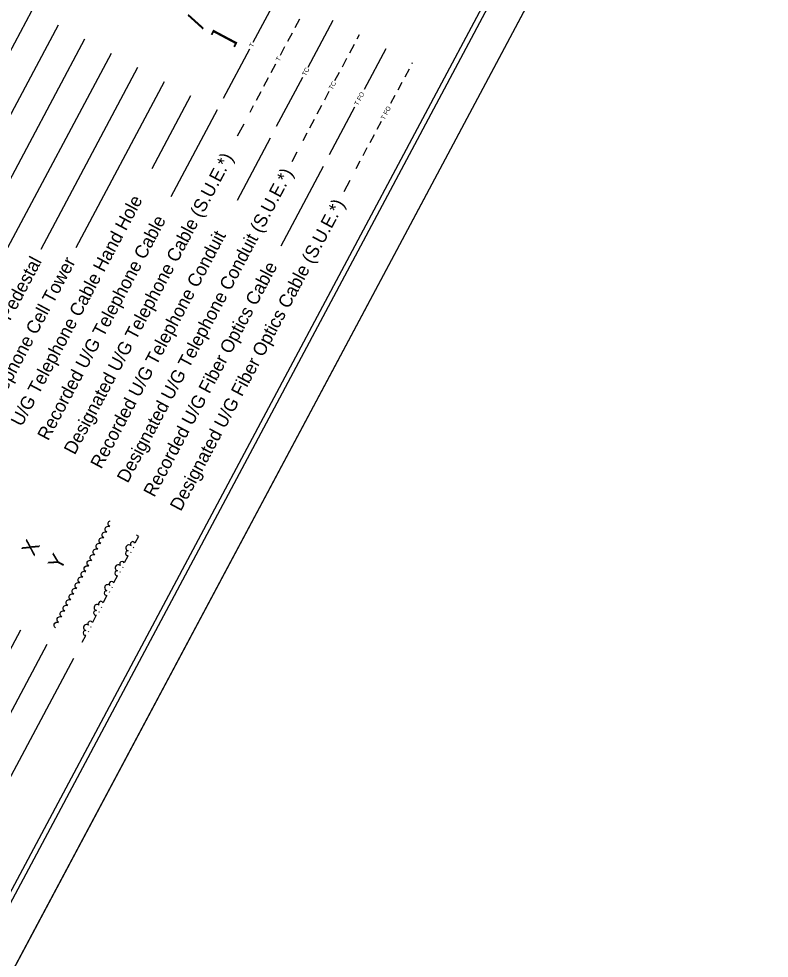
# Model space of a CAD drawing. Extents: x 1970823 to 1988115, y 770601 to 786368.
# Drawn here: x 1980773 to 1981272, y 778443 to 779069 of the extents above; entities that cross this region are included whole.
import ezdxf

# ---------------------------------------------------------------- set-up
doc = ezdxf.new("R2010")
doc.units = 0
for name, color, linetype in [('Sheet Cutting Line CELL', 7, 'Continuous'), ('Sheet Plot Border Inside CELL', 7, 'Continuous'), ('Sheet Plot Border Outside CELL', 7, 'Continuous'), ('Sheet Symbology CELL', 7, 'Continuous')]:
    doc.layers.add(name, color=color, linetype=linetype)

msp = doc.modelspace()

# ---------------------------------------------------------------- linework, layer by layer
at = {"layer": 'Sheet Cutting Line CELL'}
msp.add_line((1980480.43, 777893.78), (1981272.39, 779379.94), dxfattribs=at)
at = {"layer": 'Sheet Plot Border Inside CELL'}
msp.add_lwpolyline([(1980466.73, 777915.81), (1981250.46, 779386.52), (1980319.32, 779882.72), (1979535.59, 778412.01)], close=True, dxfattribs=at)
at = {"layer": 'Sheet Plot Border Outside CELL'}
msp.add_lwpolyline([(1980480.43, 777893.78), (1981272.39, 779379.94), (1980301.63, 779897.25), (1979509.67, 778411.1)], close=True, dxfattribs=at)
at = {"layer": 'Sheet Symbology CELL'}
for p, q in [((1980928.96, 779052.97), (1980946.77, 779086.4)), ((1980781.36, 779073.68), (1980728.74, 778974.94)), ((1980799.01, 779064.28), (1980751.01, 778974.21)), ((1980956.86, 779062.81), (1980959.92, 779068.54)), ((1980965.42, 779036.33), (1980982.07, 779067.59)), ((1980951.92, 779053.54), (1980954.98, 779059.28)), ((1980998.12, 779055.17), (1980999.72, 779058.18)), ((1980816.66, 779054.87), (1980751.82, 778933.21)), ((1980993.18, 779045.9), (1980996.24, 779051.64)), ((1980834.31, 779045.47), (1980763.53, 778912.65)), ((1980909.15, 779015.8), (1980926.61, 779048.56)), ((1980946.99, 779044.27), (1980950.04, 779050.01)), ((1981002.97, 779021.75), (1981017.37, 779048.78)), ((1980940.92, 779032.89), (1980943.98, 779038.63)), ((1980988.24, 779036.64), (1980991.3, 779042.37)), ((1981034.71, 779038.78), (1981035.02, 779039.37)), ((1980851.96, 779036.06), (1980787.45, 778915.01)), ((1980983.3, 779027.37), (1980986.36, 779033.11)), ((1981030.01, 779029.96), (1981032.83, 779035.25)), ((1980869.61, 779026.65), (1980810.72, 778916.14)), ((1980935.98, 779023.62), (1980939.04, 779029.36)), ((1980944.45, 778996.99), (1980961.89, 779029.72)), ((1981025.31, 779021.13), (1981028.13, 779026.43)), ((1980931.04, 779014.36), (1980934.1, 779020.09)), ((1980976.48, 779014.57), (1980979.54, 779020.31)), ((1980887.26, 779017.25), (1980861.38, 778968.68)), ((1981020.6, 779012.31), (1981023.43, 779017.6)), ((1980904.91, 779007.84), (1980874.08, 778949.98)), ((1980926.8, 779006.39), (1980929.16, 779010.83)), ((1980971.55, 779005.31), (1980974.6, 779011.04)), ((1980979.75, 778978.17), (1980996.62, 779009.83)), ((1980966.61, 778996.04), (1980969.67, 779001.78)), ((1980922.56, 778998.44), (1980918.26, 778990.37)), ((1981011.43, 778995.1), (1981014.25, 779000.4)), ((1980940.21, 778989.03), (1980918.14, 778947.62)), ((1980962.1, 778987.58), (1980964.73, 778992.51)), ((1981006.73, 778986.28), (1981009.55, 778991.57)), ((1981002.03, 778977.45), (1981004.85, 778982.75)), ((1980957.86, 778979.63), (1980954.54, 778973.39)), ((1980975.51, 778970.22), (1980947.28, 778917.25)), ((1980997.4, 778968.77), (1981000.15, 778973.92)), ((1980993.16, 778960.81), (1980989.14, 778953.26)), ((1980832.36, 778732.9), (1980832.8, 778733.74)), ((1980832.38, 778731.99), (1980832.36, 778732.9)), ((1980832.67, 778731.15), (1980832.38, 778731.99)), ((1980832.8, 778733.74), (1980833.62, 778734.21)), ((1980833.62, 778734.21), (1980833.69, 778734.23)), ((1980828.36, 778725.4), (1980828.81, 778726.24)), ((1980828.81, 778726.24), (1980829.62, 778726.71)), ((1980829.62, 778726.71), (1980830.46, 778726.89)), ((1980830.36, 778729.15), (1980830.81, 778729.99)), ((1980830.38, 778728.24), (1980830.36, 778729.15)), ((1980830.67, 778727.4), (1980830.38, 778728.24)), ((1980830.46, 778726.89), (1980831.3, 778726.67)), ((1980831.37, 778726.69), (1980830.67, 778727.4)), ((1980830.81, 778729.99), (1980831.62, 778730.46)), ((1980831.62, 778730.46), (1980832.46, 778730.64)), ((1980832.46, 778730.64), (1980833.3, 778730.42)), ((1980833.37, 778730.44), (1980832.67, 778731.15)), ((1980826.36, 778721.65), (1980826.81, 778722.49)), ((1980826.38, 778720.73), (1980826.36, 778721.65)), ((1980826.67, 778719.9), (1980826.38, 778720.73)), ((1980827.37, 778719.19), (1980826.67, 778719.9)), ((1980826.81, 778722.49), (1980827.63, 778722.96)), ((1980827.63, 778722.96), (1980828.46, 778723.14)), ((1980828.38, 778724.49), (1980828.36, 778725.4)), ((1980828.67, 778723.65), (1980828.38, 778724.49)), ((1980828.46, 778723.14), (1980829.3, 778722.92)), ((1980829.37, 778722.94), (1980828.67, 778723.65)), ((1980850.31, 778719.71), (1980852.66, 778724.12)), ((1980822.36, 778714.15), (1980822.81, 778714.99)), ((1980822.38, 778713.23), (1980822.36, 778714.15)), ((1980822.68, 778712.4), (1980822.38, 778713.23)), ((1980822.81, 778714.99), (1980823.63, 778715.46)), ((1980823.63, 778715.46), (1980824.46, 778715.64)), ((1980824.36, 778717.9), (1980824.81, 778718.74)), ((1980824.38, 778716.98), (1980824.36, 778717.9)), ((1980824.67, 778716.15), (1980824.38, 778716.98)), ((1980824.46, 778715.64), (1980825.3, 778715.42)), ((1980825.37, 778715.44), (1980824.67, 778716.15)), ((1980824.81, 778718.74), (1980825.63, 778719.21)), ((1980825.63, 778719.21), (1980826.46, 778719.39)), ((1980826.46, 778719.39), (1980827.3, 778719.17)), ((1980847.44, 778713.25), (1980847.67, 778713.7)), ((1980849.08, 778716.34), (1980849.32, 778716.78)), ((1980818.37, 778706.65), (1980818.81, 778707.49)), ((1980818.81, 778707.49), (1980819.63, 778707.96)), ((1980819.63, 778707.96), (1980820.46, 778708.14)), ((1980820.37, 778710.4), (1980820.81, 778711.24)), ((1980820.39, 778709.48), (1980820.37, 778710.4)), ((1980820.68, 778708.65), (1980820.39, 778709.48)), ((1980820.46, 778708.14), (1980821.31, 778707.92)), ((1980821.37, 778707.94), (1980820.68, 778708.65)), ((1980820.81, 778711.24), (1980821.63, 778711.71)), ((1980821.63, 778711.71), (1980822.46, 778711.89)), ((1980822.46, 778711.89), (1980823.31, 778711.67)), ((1980823.37, 778711.69), (1980822.68, 778712.4)), ((1980843.26, 778706.47), (1980845.61, 778710.89)), ((1980816.37, 778702.9), (1980816.81, 778703.74)), ((1980816.39, 778701.98), (1980816.37, 778702.9)), ((1980816.68, 778701.15), (1980816.39, 778701.98)), ((1980817.38, 778700.43), (1980816.68, 778701.15)), ((1980816.81, 778703.74), (1980817.63, 778704.21)), ((1980817.63, 778704.21), (1980818.46, 778704.39)), ((1980818.39, 778705.73), (1980818.37, 778706.65)), ((1980818.68, 778704.9), (1980818.39, 778705.73)), ((1980818.46, 778704.39), (1980819.31, 778704.16)), ((1980819.38, 778704.19), (1980818.68, 778704.9)), ((1980842.03, 778703.1), (1980842.26, 778703.55)), ((1980812.37, 778695.4), (1980812.82, 778696.24)), ((1980812.39, 778694.48), (1980812.37, 778695.4)), ((1980812.68, 778693.64), (1980812.39, 778694.48)), ((1980812.82, 778696.24), (1980813.63, 778696.71)), ((1980813.63, 778696.71), (1980814.47, 778696.89)), ((1980814.37, 778699.15), (1980814.82, 778699.99)), ((1980814.39, 778698.23), (1980814.37, 778699.15)), ((1980814.68, 778697.4), (1980814.39, 778698.23)), ((1980814.47, 778696.89), (1980815.31, 778696.66)), ((1980815.38, 778696.68), (1980814.68, 778697.4)), ((1980814.82, 778699.99), (1980815.63, 778700.46)), ((1980815.63, 778700.46), (1980816.47, 778700.64)), ((1980816.47, 778700.64), (1980817.31, 778700.41)), ((1980836.2, 778693.24), (1980838.55, 778697.65)), ((1980840.38, 778700.02), (1980840.62, 778700.46)), ((1980808.37, 778687.9), (1980808.82, 778688.73)), ((1980808.82, 778688.73), (1980809.64, 778689.21)), ((1980809.64, 778689.21), (1980810.47, 778689.39)), ((1980810.37, 778691.65), (1980810.82, 778692.49)), ((1980810.39, 778690.73), (1980810.37, 778691.65)), ((1980810.68, 778689.89), (1980810.39, 778690.73)), ((1980810.47, 778689.39), (1980811.31, 778689.16)), ((1980811.38, 778689.18), (1980810.68, 778689.89)), ((1980810.82, 778692.49), (1980811.64, 778692.96)), ((1980811.64, 778692.96), (1980812.47, 778693.14)), ((1980812.47, 778693.14), (1980813.31, 778692.91)), ((1980813.38, 778692.93), (1980812.68, 778693.64)), ((1980834.98, 778689.87), (1980835.21, 778690.31)), ((1980805.64, 778681.7), (1980806.47, 778681.88)), ((1980806.37, 778684.15), (1980806.82, 778684.98)), ((1980806.39, 778683.23), (1980806.37, 778684.15)), ((1980806.69, 778682.39), (1980806.39, 778683.23)), ((1980806.47, 778681.88), (1980807.32, 778681.66)), ((1980807.38, 778681.68), (1980806.69, 778682.39)), ((1980806.82, 778684.98), (1980807.64, 778685.45)), ((1980807.64, 778685.45), (1980808.47, 778685.63)), ((1980808.39, 778686.98), (1980808.37, 778687.9)), ((1980808.69, 778686.14), (1980808.39, 778686.98)), ((1980808.47, 778685.63), (1980809.31, 778685.41)), ((1980809.38, 778685.43), (1980808.69, 778686.14)), ((1980829.15, 778680), (1980831.5, 778684.41)), ((1980833.33, 778686.78), (1980833.56, 778687.22)), ((1980802.38, 778676.64), (1980802.82, 778677.48)), ((1980802.4, 778675.73), (1980802.38, 778676.64)), ((1980802.69, 778674.89), (1980802.4, 778675.73)), ((1980802.82, 778677.48), (1980803.64, 778677.95)), ((1980803.64, 778677.95), (1980804.47, 778678.13)), ((1980804.38, 778680.39), (1980804.82, 778681.23)), ((1980804.4, 778679.48), (1980804.38, 778680.39)), ((1980804.69, 778678.64), (1980804.4, 778679.48)), ((1980804.47, 778678.13), (1980805.32, 778677.91)), ((1980805.39, 778677.93), (1980804.69, 778678.64)), ((1980804.82, 778681.23), (1980805.64, 778681.7)), ((1980827.92, 778676.63), (1980828.16, 778677.07)), ((1980798.38, 778669.14), (1980798.83, 778669.98)), ((1980798.83, 778669.98), (1980799.64, 778670.45)), ((1980799.64, 778670.45), (1980800.48, 778670.63)), ((1980800.38, 778672.89), (1980800.82, 778673.73)), ((1980800.4, 778671.98), (1980800.38, 778672.89)), ((1980800.69, 778671.14), (1980800.4, 778671.98)), ((1980800.48, 778670.63), (1980801.32, 778670.41)), ((1980801.39, 778670.43), (1980800.69, 778671.14)), ((1980800.82, 778673.73), (1980801.64, 778674.2)), ((1980801.64, 778674.2), (1980802.47, 778674.38)), ((1980802.47, 778674.38), (1980803.32, 778674.16)), ((1980803.39, 778674.18), (1980802.69, 778674.89)), ((1980822.09, 778666.76), (1980824.45, 778671.17)), ((1980826.27, 778673.54), (1980826.51, 778673.98)), ((1980796.38, 778665.39), (1980796.83, 778666.23)), ((1980796.4, 778664.47), (1980796.38, 778665.39)), ((1980796.69, 778663.64), (1980796.4, 778664.47)), ((1980797.39, 778662.93), (1980796.69, 778663.64)), ((1980796.83, 778666.23), (1980797.64, 778666.7)), ((1980797.64, 778666.7), (1980798.48, 778666.88)), ((1980798.4, 778668.23), (1980798.38, 778669.14)), ((1980798.69, 778667.39), (1980798.4, 778668.23)), ((1980798.48, 778666.88), (1980799.32, 778666.66)), ((1980799.39, 778666.68), (1980798.69, 778667.39)), ((1980820.87, 778663.39), (1980821.1, 778663.83)), ((1980773.91, 778661.4), (1980688.73, 778501.55)), ((1980815.04, 778653.52), (1980817.39, 778657.93)), ((1980819.22, 778660.3), (1980819.46, 778660.74)), ((1980791.56, 778651.99), (1980691.54, 778464.29)), ((1980809.21, 778642.59), (1980724.03, 778482.74))]:
    msp.add_line(p, q, dxfattribs=at)
msp.add_lwpolyline([(1980315.7, 779870.49), (1979610.27, 778546.72), (1980536.01, 778053.4), (1981241.44, 779377.17)], close=True, dxfattribs=at)
for centre, radius, start, end in [((1980848.69, 778718.82), 1.58, 22.71557, 223.51214), ((1980852.45, 778725.88), 1.58, 218.19811, 265.69608), ((1980845.39, 778712.64), 1.58, 80.38204, 281.17861), ((1980846.16, 778716.2), 2.06, 47.91085, 255.98334), ((1980841.63, 778705.58), 1.58, 22.71557, 223.51214), ((1980838.34, 778699.4), 1.58, 80.38204, 281.17861), ((1980839.1, 778702.96), 2.06, 47.91085, 255.98334), ((1980832.05, 778689.72), 2.06, 47.91085, 255.98334), ((1980834.58, 778692.34), 1.58, 22.71557, 223.51214), ((1980831.29, 778686.16), 1.58, 80.38204, 281.17861), ((1980824.99, 778676.49), 2.06, 47.91085, 255.98334), ((1980827.52, 778679.1), 1.58, 22.71557, 223.51214), ((1980824.23, 778672.93), 1.58, 80.38204, 281.17861), ((1980817.94, 778663.25), 2.06, 47.91085, 255.98334), ((1980820.47, 778665.87), 1.58, 22.71557, 223.51214), ((1980817.18, 778659.69), 1.58, 80.38204, 281.17861)]:
    msp.add_arc(centre, radius, start, end, dxfattribs=at)

# ---------------------------------------------------------------- texts
for s, height, p in [('/', 12.5, (1980895.24, 779061.45)), (']', 13.5, (1980913.09, 779051.37)), ('T', 3, (1980928.66, 779049.22)), ('T', 3, (1980946.36, 779039.91)), ('TC', 3, (1980963.85, 779030.2)), ('TC', 3, (1980981.62, 779021.02)), ('T FO', 3, (1980998.65, 779010.45)), ('T FO', 3, (1981016.28, 779001.01)), ('Designated U/G Telephone Cable (S.U.E.*)', 8.75, (1980810.08, 778777.7)), ('Designated U/G Telephone Conduit (S.U.E.*)', 8.75, (1980845.38, 778758.89)), ('U/G Telephone Cable Hand Hole', 8.75, (1980774.77, 778796.52)), ('Designated U/G Fiber Optics Cable (S.U.E.*)', 8.75, (1980880.68, 778740.08)), ('Recorded U/G Telephone Cable', 8.75, (1980792.43, 778787.11)), ('Recorded U/G Telephone Conduit', 8.75, (1980827.73, 778768.3)), ('Telephone Pedestal', 8.75, (1980739.47, 778815.32)), ('Telephone Cell Tower', 8.75, (1980757.12, 778805.92)), ('Recorded U/G Fiber Optics Cable', 8.75, (1980863.03, 778749.49)), ('X', 10, (1980782.96, 778710.28)), ('Y', 10, (1980800.61, 778700.87))]:
    msp.add_text(s, height=height, rotation=61.94709, dxfattribs=at).set_placement(p)

doc.saveas('drawing.dxf')
